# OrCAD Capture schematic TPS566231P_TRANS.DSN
size C; title: TPS566231P, 3-V to 18-V Input, 6-A Synchronous; rev: 1.0; note: Datasheet: SLUSDQ7A     EVM: SLUUC76A; note: Synchronous Step Down Converter; note: Step-Down Voltage Regulator
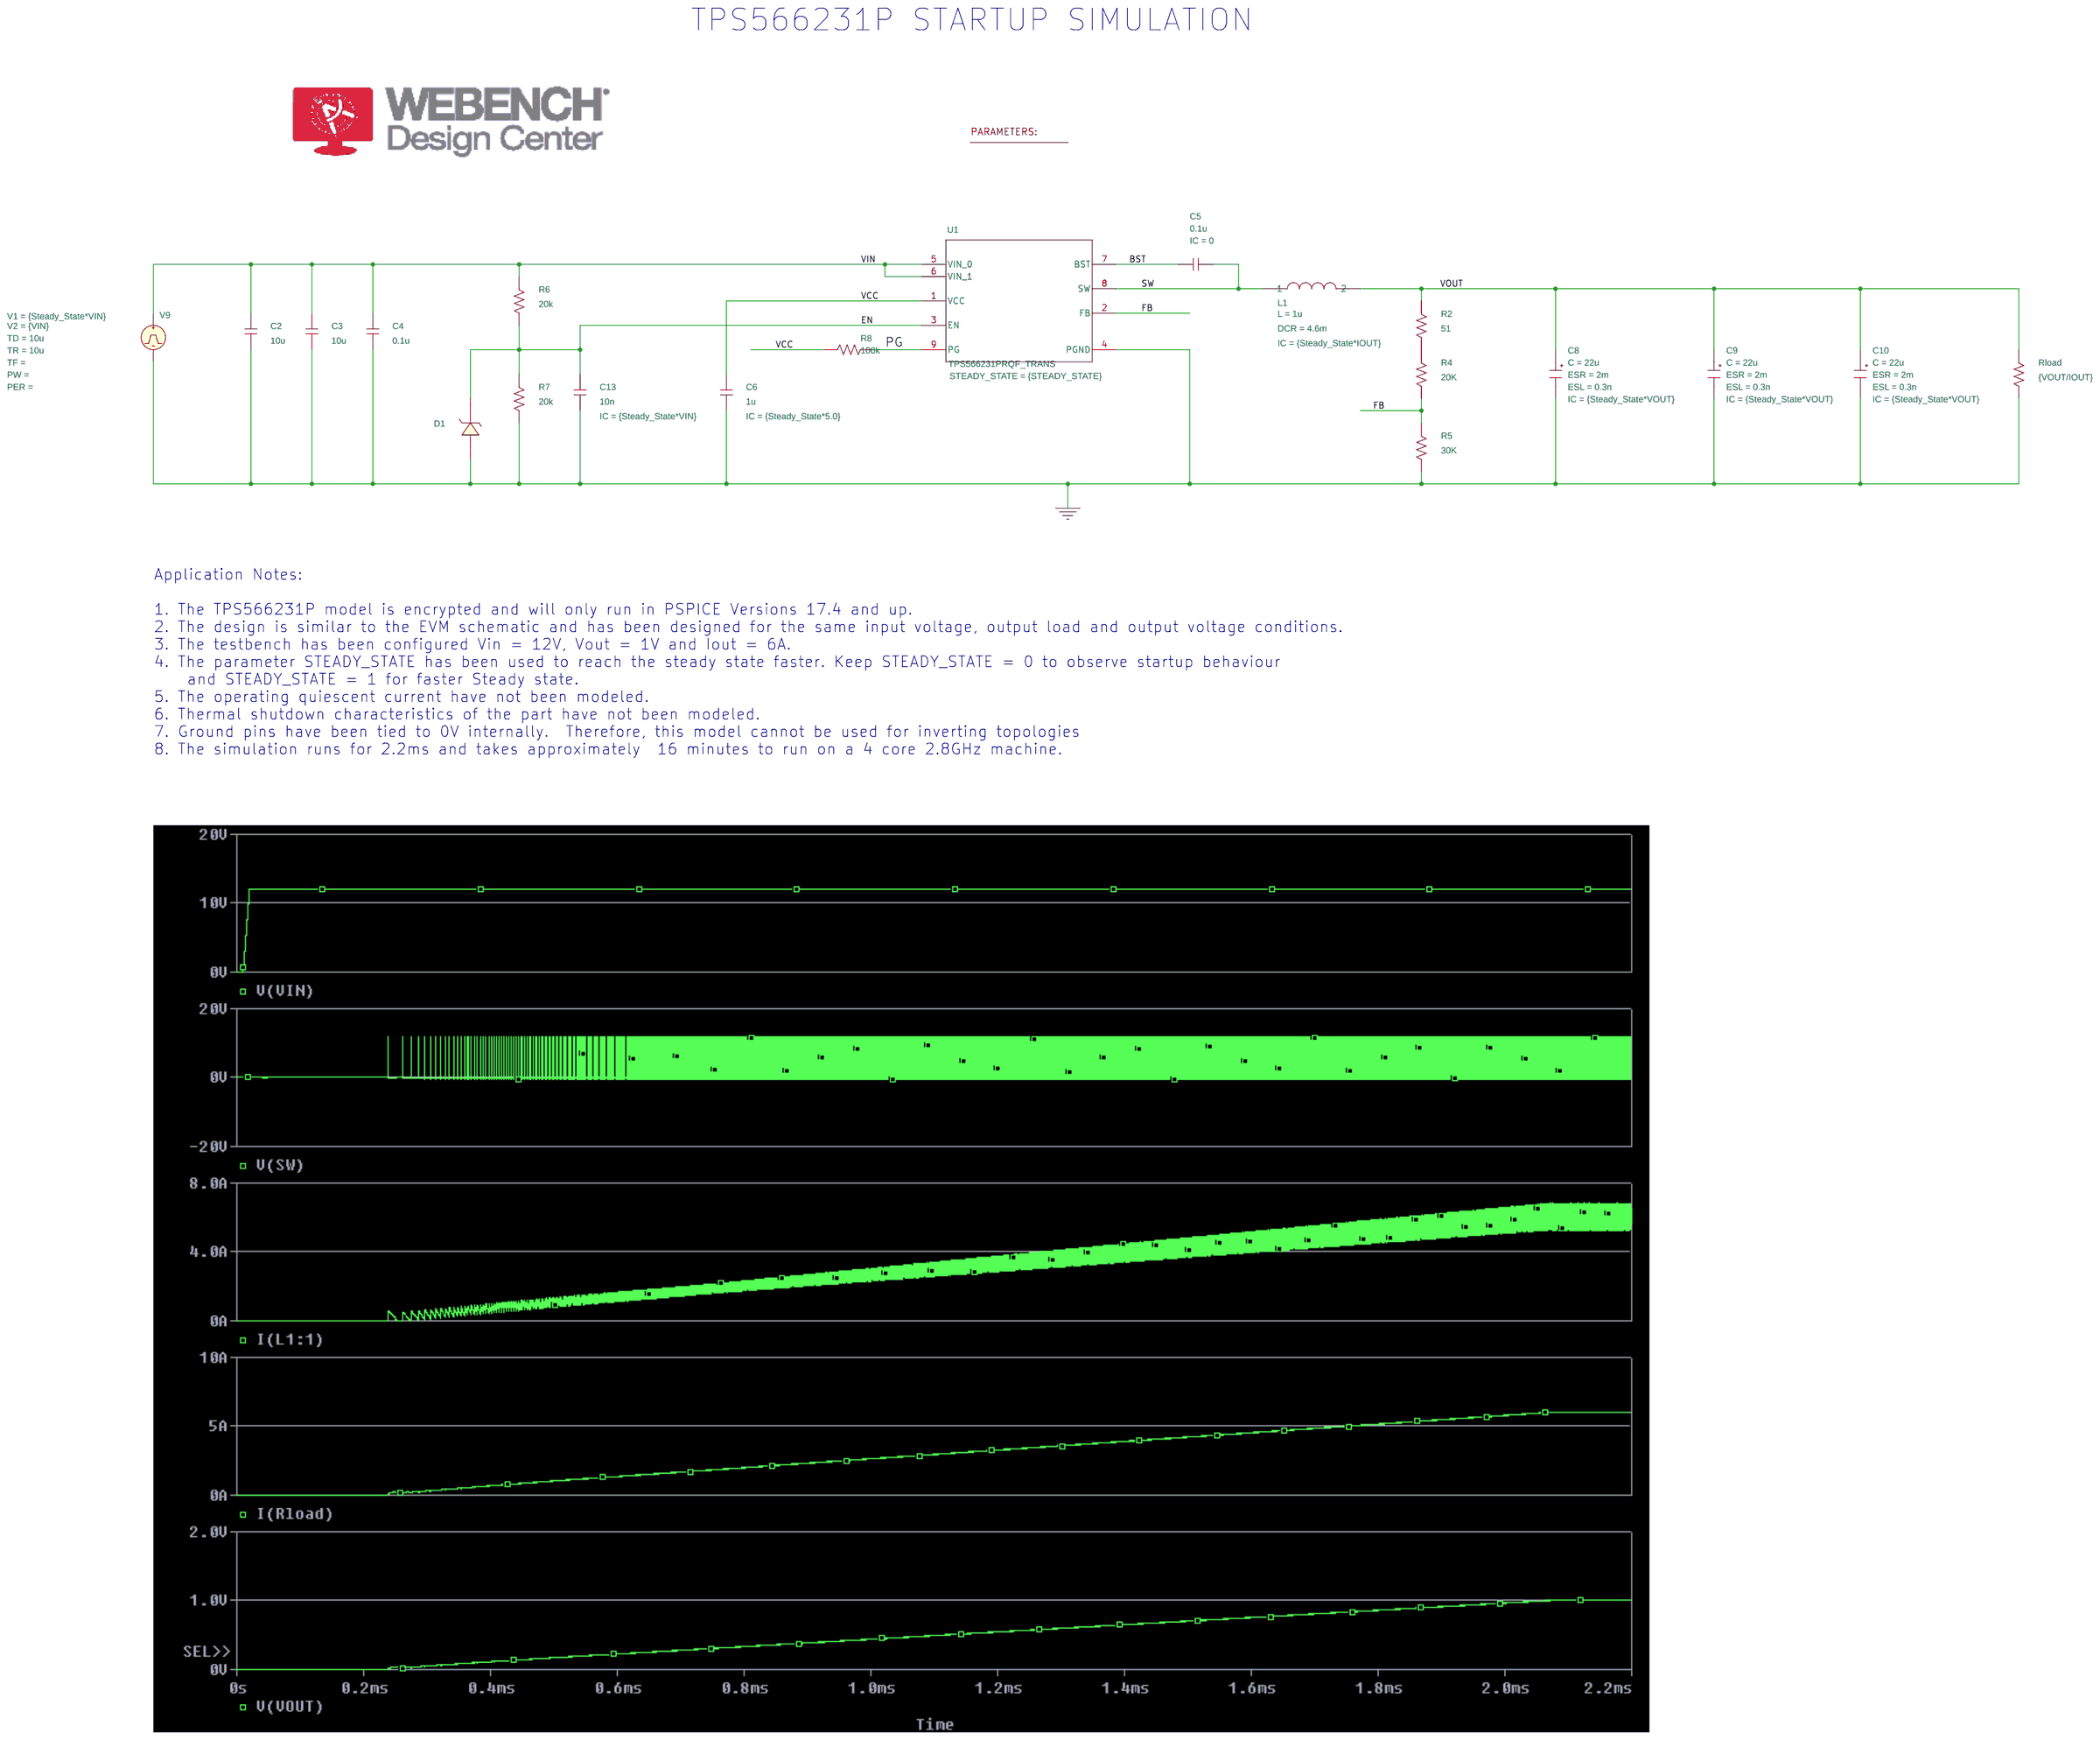
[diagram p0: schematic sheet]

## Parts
3  PARAM
C2  10u  [RAD/CK05]
C3  10u  [RAD/CK05]
C4  0.1u  [RAD/CK05]
C5  0.1u  [RAD/CK05]
C6  1u  [RAD/CK05]
C8  CESR
C9  CESR
C10  CESR
C13  10n  [RAD/CK05]
D1  DI_MMSZ5231B
L1  LDCR
R2  51  [AX/RC05]
R4  20K  [AX/RC05]
R5  30K  [AX/RC05]
R6  20k  [AX/RC05]
R7  20k  [AX/RC05]
R8  100k  [AX/RC05]
Rload  {VOUT/IOUT}  [AX/RC05]
U1  TPS566231PRQF_TRANS  [RQF0009A-MFG]
V9  VPULSE

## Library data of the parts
3 = PARAM: IOUT: 6; Steady_State: 0; VIN: 12; VOUT: 1
C2-C4 = C
C5 = C: IC: 0
C6 = C: IC: {Steady_State*5.0}
C8-C10 = CESR_0: C: 22u; ESL: 0.3n; ESR: 2m; IC: {Steady_State*VOUT}
C13 = C: IC: {Steady_State*VIN}
D1 = DI_MMSZ5231B
L1 = LDCR: DCR: 4.6m; IC: {Steady_State*IOUT}; L: 1u
R2 R4-R8 Rload = R
U1 = TPS566231PRQF_TRANS: STEADY_STATE: {STEADY_STATE}
V9 = VPULSE: TD: 10u; TR: 10u; V1: {Steady_State*VIN}; V2: {VIN}

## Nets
VCC: C6.1 R8.1 U1.1(VCC)
VIN: C2.1 C3.1 C4.1 R6.1 U1.5(VIN_0) U1.6(VIN_1) V9.1(+)
0: C2.2 C3.2 C4.2 C6.2 C8.2(OUT) C9.2(OUT) C10.2(OUT) C13.2 D1.2(A) R5.2 R7.2 Rload.2 U1.4(PGND) V9.2(-)
BST: C5.2 U1.7(BST)
EN: C13.1 D1.1(C) R6.2 R7.1 U1.3(EN)
FB: R4.2 R5.1 U1.2(FB)
PG: R8.2 U1.9(PG)
SW: C5.1 L1.1 U1.8(SW)
VOUT: C8.1(IN) C9.1(IN) C10.1(IN) L1.2 R2.1 Rload.1
N16770002: R2.2 R4.1

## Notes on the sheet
- TPS566231P STARTUP SIMULATION
- Application Notes:
  1. The TPS566231P model is encrypted and will only run in PSPICE Versions 17.4 and up.
  2. The design is similar to the EVM schematic and has been designed for the same input voltage, output load and output voltage conditions.
  3. The testbench has been configured Vin = 12V, Vout = 1V and Iout = 6A.
  4. The parameter STEADY_STATE has been used to reach the steady state faster. Keep STEADY_STATE = 0 to observe startup behaviour
      and STEADY_STATE = 1 for faster Steady state.
  5. The operating quiescent current have not been modeled.
  6. Thermal shutdown characteristics of the part have not been modeled.
  7. Ground pins have been tied to 0V internally.  Therefore, this model cannot be used for inverting topologies
  8. The simulation runs for 2.2ms and takes approximately  16 minutes to run on a 4 core 2.8GHz machine.
